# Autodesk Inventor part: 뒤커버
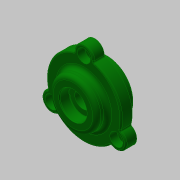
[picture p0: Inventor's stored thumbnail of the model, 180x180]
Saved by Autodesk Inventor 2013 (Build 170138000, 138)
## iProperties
Created: 2016-05
Part Number: 뒤커버
Document SubType Name: Modeling
Designer: mduedu
Density: 2.71 g/cm^3
Material: 알루미늄 6061
Author: mduedu
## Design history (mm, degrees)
sketch "스케치1"
  geometry: C1 r 20 at (0, 0); C2 r 27.5 at (0, 0); 1 further point
  constraints: 2 centre point, 2 coincident
  dimensions: "d33" = 55 diameter of C2; "d34" = 40 diameter of C1
extrude "돌출1" new body sketch "스케치1" distance "d0" = 8; taper "d1" = 0 deg
extrude "돌출2" join sketch "스케치1" distance "d2" = 8; taper "d3" = 0 deg; dims "d35" = 9, "d36" = 0
sketch "스케치6"
  geometry: C1 r 17.5 at (0, 0); 2 further points
  constraints: 2 coincident, 1 centre point
  dimensions: "d42" = 35 diameter of C1
extrude "돌출4" join sketch "스케치6" distance "d43" = 8; taper "d44" = 0 deg
sketch "스케치4"
  geometry: L1 (0, -9)-(0, 16); L2 (-15, -9)-(-15, 0); L3 (-15, 0)-(-10, 0); L4 (-10, 0)-(-10, 3); L5 (-10, 3)-(-6, 3); L6 (-6, 3)-(-6, 8.7); L7 (-6, 8.7)-(-10, 8.7); L8 (-10, 8.7)-(-10, 16); L9 (20, -9)-(-20, -9) reference; L10 (17.5, 16)-(-17.5, 16) reference; 1 further point
  constraints: 16 end point, 6 parallel, 3 point on line, 2 midpoint, 2 perpendicular, 1 vertical
  dimensions: "d15" = 30 diameter of L2 L1; "d16" = 20 diameter of L8 L1; "d18" = 9 distance of L2.start L2.end; "d19" = 3 distance of L3.end L4.end; "d20" = 20 diameter of L4 L1; "d21" = 12 diameter of L6 L1; "d45" = 7.3 distance of L7.end L8.end
revolve "회전1" sketch "스케치4" stored, may be unused: angle "d22" = 90 deg
fillet "모깎기2" dims "d23" = 3
fillet "모깎기3" dims "d24" = 0.3
chamfer "모따기2" distance "d46" = 1; stored, may be unused: second distance "d47" = 2, angle "d48" = 45 deg
sketch "스케치7"
  geometry: C1 r 7 at (0, 27.5); 2 further points
  constraints: 3 vertical alignment, 1 centre point, 2 other
  dimensions: "d54" = 14 diameter of C1
extrude "돌출5" join sketch "스케치7" stored distance "d55" = 10; taper "d56" = 0 deg
fillet "모깎기6" dims "d57" = 1
sketch "스케치10"
  geometry: C1 r 17.5 at (0, 0) reference; A1 r 27.5 centre (0, 0) between (26.718, -6.513) and (7.718, 26.395) reference; A2 r 1 centre (7.999, 27.355) between (6.999, 27.373) and (7.718, 26.395) reference; A3 r 7 centre (0, 27.5) between (6.999, 27.373) and (-6.999, 27.373) reference; A4 r 1 centre (-7.999, 27.355) between (-7.718, 26.395) and (-6.999, 27.373) reference; A5 r 27.5 centre (0, 0) between (-7.718, 26.395) and (-26.718, -6.513) reference; A6 r 1 centre (-27.689, -6.75) between (-27.205, -7.625) and (-26.718, -6.513) reference; A7 r 7 centre (-23.816, -13.75) between (-27.205, -7.625) and (-20.206, -19.748) reference; A8 r 1 centre (-19.69, -20.604) between (-19, -19.881) and (-20.206, -19.748) reference; A9 r 27.5 centre (0, 0) between (-19, -19.881) and (19, -19.881) reference; A10 r 1 centre (19.69, -20.604) between (20.206, -19.748) and (19, -19.881) reference; A11 r 7 centre (23.816, -13.75) between (20.206, -19.748) and (27.205, -7.625) reference; A12 r 1 centre (27.689, -6.75) between (26.718, -6.513) and (27.205, -7.625) reference; 4 further points
  constraints: 3 coincident
hole "구멍3" sketch "스케치10" at (0, 27.5), (-23.816, -13.75), (23.816, -13.75) diameter "d81" = 5.5; stored, may be unused: countersink angle "d85" = 90 deg, drill point angle "d87" = 118 deg; dims "d82" = 6, "d83" = 9.5, "d84" = 5.4, "d86" = 8
fillet "모깎기7" dims "d61" = 1
fillet "모깎기8" dims "d88" = 3
chamfer "모따기3" distance "d76" = 0.7; stored, may be unused: second distance "d77" = 2, angle "d78" = 30 deg
node "솔리드1"
pattern_circular "원형 패턴1" dims angle "d59" = 360 deg
node "투영된 루프1"
